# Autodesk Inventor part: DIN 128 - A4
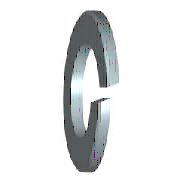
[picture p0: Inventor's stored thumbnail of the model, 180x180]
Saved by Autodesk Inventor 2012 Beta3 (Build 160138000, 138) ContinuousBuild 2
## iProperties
Created: 2010-11
Part Number: DIN 128 - A4
Material: Steel, Mild
Description: Spring Washer
Document SubType Name: Modeling
Standard: DIN 128
Designer: Beta-8540w
Standard Revision: 1994
Standards Organization: DIN
Language: en-US
Size Designation: A4
Categories: <MemberInstance><Categories><Category DisplayName="Fasteners" InternalName="e4da775c-781d-43d5-af7c-5136215cf5a6" Mnemonic="FSTN"><Category DisplayName="Washers
Density: 1 g/cm^3
IsCustomPart: 0
Author: Beta-8540w
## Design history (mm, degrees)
body "Solid1"
sketch "Sketch1"
  geometry: C1 r 3.8 at (0, 0); C2 r 2.2 at (0, 0); 1 further point
  constraints: 2 centre point, 2 coincident
  dimensions: "d0" = 4.4 diameter of C2 (= SD1); "d1" = 7.6 diameter of C1 (= SD2)
extrude "Body" new body sketch "Sketch1" distance "d2" = 0.8 (= SD); taper "d3" = 0 deg
sketch "Sketch2"
  geometry: L1 (0, -2.2)-(0, 2.2) reference; L2 (0.8, 3.8)-(0.8, -3.8) reference; L3 (-1.2, 0)-(7.2, 0) reference; L4 (0, -0.16)-(0.8, 0.302); L5 (0, 0.16)-(0.8, 0.622)
  constraints: 4 end point, 4 point on line, 1 parallel
  dimensions: "d4" = 0.16 distance from line of L3 L4.start (= 0.2 x SD); "d5" = 0.16 distance from line of L3 L5.start (= 0.2 x SD); "d6" = 60 deg angle of L2 L4 (= FAWI)
extrude "Cut" cut sketch "Sketch2" stored distance "d7" = 0.8 (= SD); taper "d8" = 0 deg
workaxis "Work Axis1"
workplane "Work Plane1"
fillet "Fillet" dims "d13" = 0.2 (= R)
other parameters: "SD1" = 4.4 [user parameter; used in 1 equation term], "SD2" = 7.6 [user parameter; used in 1 equation term], "SD" = 0.8 [user parameter; used in 4 equation terms], "FAWI" = 60 deg [user parameter; used in 1 equation term], "d9" = 0, "d10" = 0, "d11" = 0, "d12" = 0, "R" = 0.2 [user parameter; used in 1 equation term], "NND" = 4 [user parameter]
